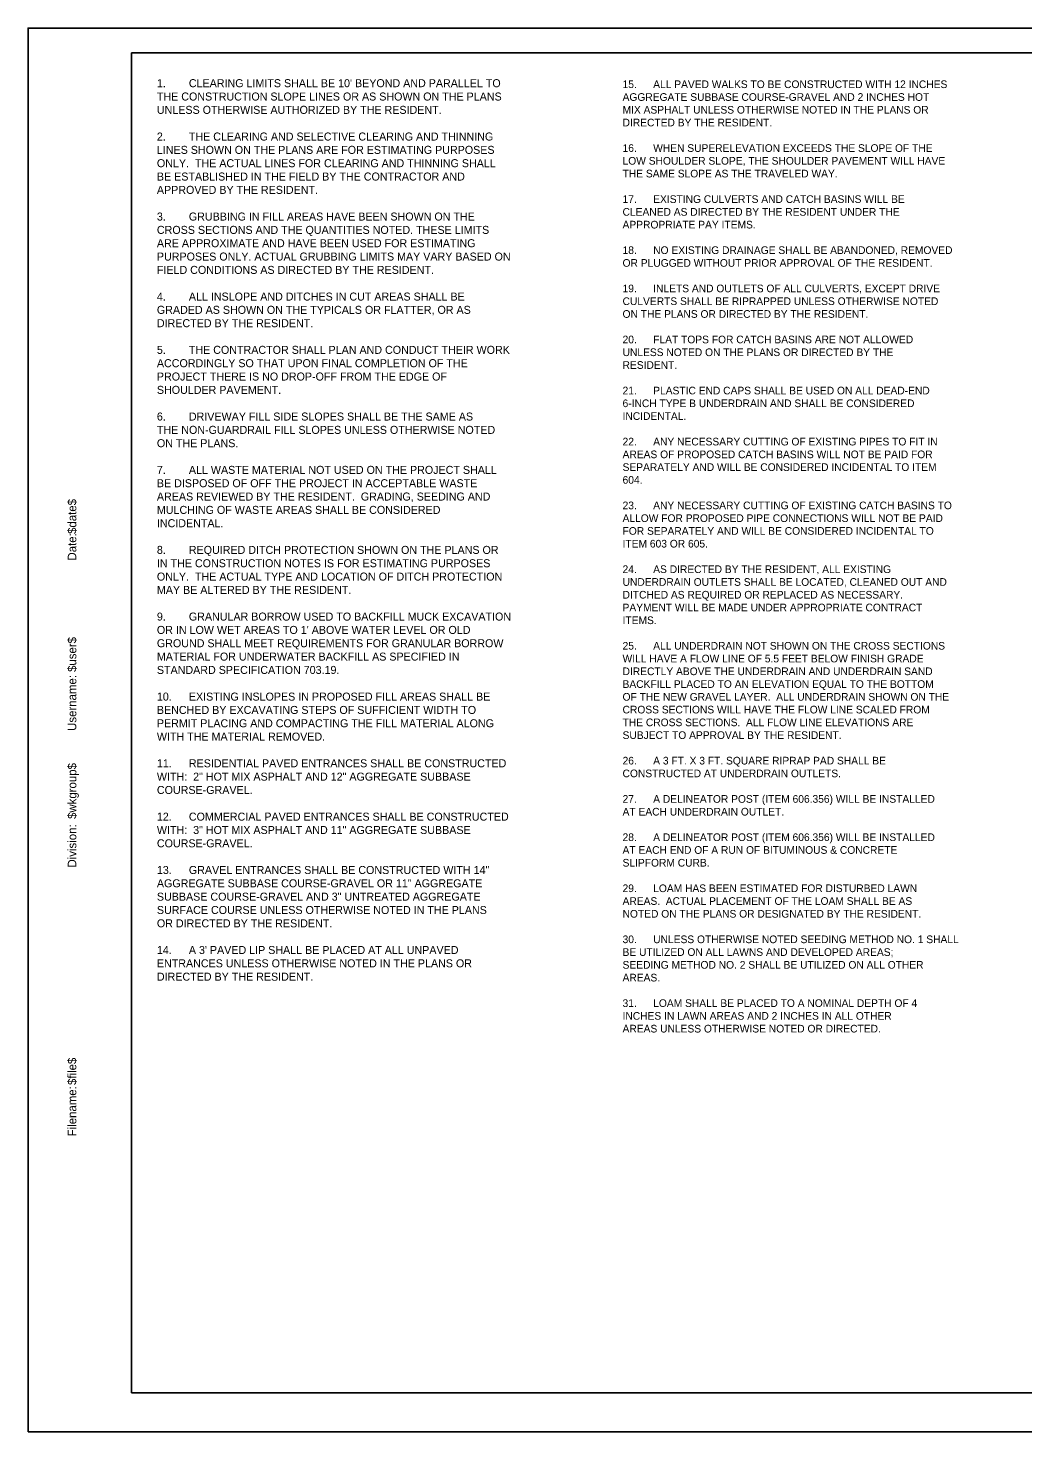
# Model space of a CAD drawing. Extents: x 2075518.1 to 2075585.6, y 1172412.5 to 1172434.5.
# Drawn here: x 2075518.14 to 2075533.73, y 1172412.49 to 1172434.49 of the extents above; entities that cross this region are included whole.
import ezdxf

# ---------------------------------------------------------------- set-up
doc = ezdxf.new("R2010")
doc.units = 0
for name, color, linetype in [('ANNOTATION', 7, 'Continuous'), ('Border', 7, 'Continuous'), ('PLOT BOUNDARY', 7, 'Continuous')]:
    doc.layers.add(name, color=color, linetype=linetype)

msp = doc.modelspace()

# ---------------------------------------------------------------- linework, layer by layer
at = {"layer": 'Border'}
for p, q in [((2075551.755, 1172434.098), (2075519.755, 1172434.098)), ((2075519.755, 1172434.098), (2075519.755, 1172413.098)), ((2075519.755, 1172413.098), (2075551.755, 1172413.098))]:
    msp.add_line(p, q, dxfattribs=at)
at = {"layer": 'PLOT BOUNDARY'}
msp.add_lwpolyline([(2075518.136, 1172412.486), (2075552.136, 1172412.486), (2075552.136, 1172434.486), (2075518.136, 1172434.486)], close=True, dxfattribs=at)

# ---------------------------------------------------------------- texts
at = {"layer": 'ANNOTATION'}
for s, height, p in [('1.', 0.1254, (2075520.155, 1172433.56)), ("CLEARING LIMITS SHALL BE 10' BEYOND AND PARALLEL TO ", 0.12539, (2075520.656, 1172433.56)), ('THE CONSTRUCTION SLOPE LINES OR AS SHOWN ON THE PLANS ', 0.12539, (2075520.155, 1172433.351)), ('AGGREGATE SUBBASE COURSE-GRAVEL AND 2 INCHES HOT ', 0.12, (2075527.453, 1172433.346)), ('15.', 0.12, (2075527.453, 1172433.546)), ('ALL PAVED WALKS TO BE CONSTRUCTED WITH 12 INCHES ', 0.12, (2075527.933, 1172433.546)), ('UNLESS OTHERWISE AUTHORIZED BY THE RESIDENT.  ', 0.12539, (2075520.155, 1172433.142)), ('MIX ASPHALT UNLESS OTHERWISE NOTED IN THE PLANS OR ', 0.12, (2075527.453, 1172433.146)), ('DIRECTED BY THE RESIDENT.', 0.12, (2075527.453, 1172432.946)), ('2.', 0.1254, (2075520.155, 1172432.724)), ('THE CLEARING AND SELECTIVE CLEARING AND THINNING ', 0.12539, (2075520.656, 1172432.724)), ('LINES SHOWN ON THE PLANS ARE FOR ESTIMATING PURPOSES ', 0.12539, (2075520.155, 1172432.515)), ('16.', 0.12, (2075527.453, 1172432.546)), ('WHEN SUPERELEVATION EXCEEDS THE SLOPE OF THE ', 0.12, (2075527.933, 1172432.546)), ('ONLY.  THE ACTUAL LINES FOR CLEARING AND THINNING SHALL ', 0.12539, (2075520.155, 1172432.306)), ('LOW SHOULDER SLOPE, THE SHOULDER PAVEMENT WILL HAVE ', 0.12, (2075527.453, 1172432.346)), ('BE ESTABLISHED IN THE FIELD BY THE CONTRACTOR AND ', 0.12539, (2075520.155, 1172432.097)), ('THE SAME SLOPE AS THE TRAVELED WAY.', 0.12, (2075527.453, 1172432.146)), ('APPROVED BY THE RESIDENT.', 0.12539, (2075520.155, 1172431.888)), ('17.', 0.12, (2075527.453, 1172431.746)), ('EXISTING CULVERTS AND CATCH BASINS WILL BE ', 0.12, (2075527.933, 1172431.746)), ('3.', 0.1254, (2075520.155, 1172431.47)), ('GRUBBING IN FILL AREAS HAVE BEEN SHOWN ON THE ', 0.12539, (2075520.656, 1172431.47)), ('CLEANED AS DIRECTED BY THE RESIDENT UNDER THE ', 0.12, (2075527.453, 1172431.546)), ('CROSS SECTIONS AND THE QUANTITIES NOTED. THESE LIMITS ', 0.12539, (2075520.155, 1172431.261)), ('APPROPRIATE PAY ITEMS.', 0.12, (2075527.453, 1172431.346)), ('ARE APPROXIMATE AND HAVE BEEN USED FOR ESTIMATING ', 0.12539, (2075520.155, 1172431.052)), ('18.', 0.12, (2075527.453, 1172430.946)), ('NO EXISTING DRAINAGE SHALL BE ABANDONED, REMOVED ', 0.12, (2075527.933, 1172430.946)), ('PURPOSES ONLY. ACTUAL GRUBBING LIMITS MAY VARY BASED ON ', 0.12539, (2075520.155, 1172430.843)), ('OR PLUGGED WITHOUT PRIOR APPROVAL OF THE RESIDENT.', 0.12, (2075527.453, 1172430.746)), ('FIELD CONDITIONS AS DIRECTED BY THE RESIDENT. ', 0.12539, (2075520.155, 1172430.634)), ('19.', 0.12, (2075527.453, 1172430.346)), ('INLETS AND OUTLETS OF ALL CULVERTS, EXCEPT DRIVE ', 0.12, (2075527.933, 1172430.346)), ('4.', 0.1254, (2075520.155, 1172430.216)), ('ALL INSLOPE AND DITCHES IN CUT AREAS SHALL BE ', 0.12539, (2075520.656, 1172430.216)), ('CULVERTS SHALL BE RIPRAPPED UNLESS OTHERWISE NOTED ', 0.12, (2075527.453, 1172430.146)), ('GRADED AS SHOWN ON THE TYPICALS OR FLATTER, OR AS ', 0.12539, (2075520.155, 1172430.008)), ('ON THE PLANS OR DIRECTED BY THE RESIDENT.', 0.12, (2075527.453, 1172429.946)), ('DIRECTED BY THE RESIDENT.', 0.12539, (2075520.155, 1172429.799)), ('5.', 0.1254, (2075520.155, 1172429.381)), ('THE CONTRACTOR SHALL PLAN AND CONDUCT THEIR WORK ', 0.12539, (2075520.656, 1172429.381)), ('20.', 0.12, (2075527.453, 1172429.546)), ('FLAT TOPS FOR CATCH BASINS ARE NOT ALLOWED ', 0.12, (2075527.933, 1172429.546)), ('ACCORDINGLY SO THAT UPON FINAL COMPLETION OF THE ', 0.12539, (2075520.155, 1172429.172)), ('UNLESS NOTED ON THE PLANS OR DIRECTED BY THE ', 0.12, (2075527.453, 1172429.346)), ('PROJECT THERE IS NO DROP-OFF FROM THE EDGE OF ', 0.12539, (2075520.155, 1172428.963)), ('RESIDENT.', 0.12, (2075527.453, 1172429.146)), ('SHOULDER PAVEMENT. ', 0.12539, (2075520.155, 1172428.754)), ('21.', 0.12, (2075527.453, 1172428.746)), ('PLASTIC END CAPS SHALL BE USED ON ALL DEAD-END ', 0.12, (2075527.933, 1172428.746)), ('6-INCH TYPE B UNDERDRAIN AND SHALL BE CONSIDERED ', 0.12, (2075527.453, 1172428.546)), ('6.', 0.1254, (2075520.155, 1172428.336)), ('DRIVEWAY FILL SIDE SLOPES SHALL BE THE SAME AS ', 0.12539, (2075520.656, 1172428.336)), ('INCIDENTAL.', 0.12, (2075527.453, 1172428.346)), ('THE NON-GUARDRAIL FILL SLOPES UNLESS OTHERWISE NOTED ', 0.12539, (2075520.155, 1172428.127)), ('ON THE PLANS.', 0.12539, (2075520.155, 1172427.918)), ('22.', 0.12, (2075527.453, 1172427.946)), ('ANY NECESSARY CUTTING OF EXISTING PIPES TO FIT IN ', 0.12, (2075527.933, 1172427.946)), ('AREAS OF PROPOSED CATCH BASINS WILL NOT BE PAID FOR ', 0.12, (2075527.453, 1172427.746)), ('7.', 0.1254, (2075520.155, 1172427.5)), ('ALL WASTE MATERIAL NOT USED ON THE PROJECT SHALL ', 0.12539, (2075520.656, 1172427.5)), ('SEPARATELY AND WILL BE CONSIDERED INCIDENTAL TO ITEM ', 0.12, (2075527.453, 1172427.546)), ('BE DISPOSED OF OFF THE PROJECT IN ACCEPTABLE WASTE ', 0.12539, (2075520.155, 1172427.291)), ('604.', 0.12, (2075527.453, 1172427.346)), ('AREAS REVIEWED BY THE RESIDENT.  GRADING, SEEDING AND ', 0.12539, (2075520.155, 1172427.082)), ('MULCHING OF WASTE AREAS SHALL BE CONSIDERED ', 0.12539, (2075520.155, 1172426.873)), ('ALLOW FOR PROPOSED PIPE CONNECTIONS WILL NOT BE PAID ', 0.12, (2075527.453, 1172426.746)), ('23.', 0.12, (2075527.453, 1172426.946)), ('ANY NECESSARY CUTTING OF EXISTING CATCH BASINS TO ', 0.12, (2075527.933, 1172426.946)), ('INCIDENTAL.', 0.12539, (2075520.155, 1172426.664)), ('FOR SEPARATELY AND WILL BE CONSIDERED INCIDENTAL TO ', 0.12, (2075527.453, 1172426.546)), ('ITEM 603 OR 605.', 0.12, (2075527.453, 1172426.346)), ('8.', 0.1254, (2075520.155, 1172426.246)), ('REQUIRED DITCH PROTECTION SHOWN ON THE PLANS OR ', 0.12539, (2075520.656, 1172426.246)), ('IN THE CONSTRUCTION NOTES IS FOR ESTIMATING PURPOSES ', 0.12539, (2075520.155, 1172426.037)), ('24.', 0.12, (2075527.453, 1172425.946)), ('AS DIRECTED BY THE RESIDENT, ALL EXISTING ', 0.12, (2075527.933, 1172425.946)), ('ONLY.  THE ACTUAL TYPE AND LOCATION OF DITCH PROTECTION ', 0.12539, (2075520.155, 1172425.828)), ('UNDERDRAIN OUTLETS SHALL BE LOCATED, CLEANED OUT AND ', 0.12, (2075527.453, 1172425.746)), ('MAY BE ALTERED BY THE RESIDENT.', 0.12539, (2075520.155, 1172425.619)), ('DITCHED AS REQUIRED OR REPLACED AS NECESSARY.   ', 0.12, (2075527.453, 1172425.546)), ('9.', 0.1254, (2075520.155, 1172425.201)), ('GRANULAR BORROW USED TO BACKFILL MUCK EXCAVATION ', 0.12539, (2075520.656, 1172425.201)), ('PAYMENT WILL BE MADE UNDER APPROPRIATE CONTRACT ', 0.12, (2075527.453, 1172425.346)), ("OR IN LOW WET AREAS TO 1' ABOVE WATER LEVEL OR OLD ", 0.12539, (2075520.155, 1172424.992)), ('ITEMS.', 0.12, (2075527.453, 1172425.146)), ('GROUND SHALL MEET REQUIREMENTS FOR GRANULAR BORROW ', 0.12539, (2075520.155, 1172424.783)), ('MATERIAL FOR UNDERWATER BACKFILL AS SPECIFIED IN ', 0.12539, (2075520.155, 1172424.574)), ('WILL HAVE A FLOW LINE OF 5.5 FEET BELOW FINISH GRADE ', 0.12, (2075527.453, 1172424.546)), ('25.', 0.12, (2075527.453, 1172424.746)), ('ALL UNDERDRAIN NOT SHOWN ON THE CROSS SECTIONS ', 0.12, (2075527.933, 1172424.746)), ('STANDARD SPECIFICATION 703.19.', 0.12539, (2075520.155, 1172424.365)), ('DIRECTLY ABOVE THE UNDERDRAIN AND UNDERDRAIN SAND ', 0.12, (2075527.453, 1172424.346)), ('BACKFILL PLACED TO AN ELEVATION EQUAL TO THE BOTTOM ', 0.12, (2075527.453, 1172424.146)), ('10.', 0.1254, (2075520.155, 1172423.947)), ('EXISTING INSLOPES IN PROPOSED FILL AREAS SHALL BE ', 0.12539, (2075520.656, 1172423.947)), ('OF THE NEW GRAVEL LAYER.  ALL UNDERDRAIN SHOWN ON THE ', 0.12, (2075527.453, 1172423.946)), ('BENCHED BY EXCAVATING STEPS OF SUFFICIENT WIDTH TO ', 0.12539, (2075520.155, 1172423.738)), ('CROSS SECTIONS WILL HAVE THE FLOW LINE SCALED FROM ', 0.12, (2075527.453, 1172423.746)), ('PERMIT PLACING AND COMPACTING THE FILL MATERIAL ALONG ', 0.12539, (2075520.155, 1172423.529)), ('THE CROSS SECTIONS.  ALL FLOW LINE ELEVATIONS ARE ', 0.12, (2075527.453, 1172423.546)), ('WITH THE MATERIAL REMOVED.', 0.12539, (2075520.155, 1172423.32)), ('SUBJECT TO APPROVAL BY THE RESIDENT.  ', 0.12, (2075527.453, 1172423.346)), ('11.', 0.1254, (2075520.155, 1172422.902)), ('RESIDENTIAL PAVED ENTRANCES SHALL BE CONSTRUCTED ', 0.12539, (2075520.656, 1172422.902)), ('26.', 0.12, (2075527.453, 1172422.946)), ('A 3 FT. X 3 FT. SQUARE RIPRAP PAD SHALL BE ', 0.12, (2075527.933, 1172422.946)), ('WITH:  2" HOT MIX ASPHALT AND 12" AGGREGATE SUBBASE ', 0.12539, (2075520.155, 1172422.693)), ('CONSTRUCTED AT UNDERDRAIN OUTLETS.', 0.12, (2075527.453, 1172422.746)), ('COURSE-GRAVEL.', 0.12539, (2075520.155, 1172422.484)), ('27.', 0.12, (2075527.453, 1172422.346)), ('A DELINEATOR POST (ITEM 606.356) WILL BE INSTALLED ', 0.12, (2075527.933, 1172422.346)), ('AT EACH UNDERDRAIN OUTLET.', 0.12, (2075527.453, 1172422.146)), ('12.', 0.1254, (2075520.155, 1172422.066)), ('COMMERCIAL PAVED ENTRANCES SHALL BE CONSTRUCTED ', 0.12539, (2075520.656, 1172422.066)), ('WITH:  3" HOT MIX ASPHALT AND 11" AGGREGATE SUBBASE ', 0.12539, (2075520.155, 1172421.857)), ('28.', 0.12, (2075527.453, 1172421.746)), ('A DELINEATOR POST (ITEM 606.356) WILL BE INSTALLED ', 0.12, (2075527.933, 1172421.746)), ('COURSE-GRAVEL.', 0.12539, (2075520.155, 1172421.648)), ('AT EACH END OF A RUN OF BITUMINOUS & CONCRETE ', 0.12, (2075527.453, 1172421.546)), ('SLIPFORM CURB.', 0.12, (2075527.453, 1172421.346)), ('AGGREGATE SUBBASE COURSE-GRAVEL OR 11" AGGREGATE ', 0.12539, (2075520.155, 1172421.021)), ('13.', 0.1254, (2075520.155, 1172421.23)), ('GRAVEL ENTRANCES SHALL BE CONSTRUCTED WITH 14" ', 0.12539, (2075520.656, 1172421.23)), ('SUBBASE COURSE-GRAVEL AND 3" UNTREATED AGGREGATE ', 0.12539, (2075520.155, 1172420.812)), ('29.', 0.12, (2075527.453, 1172420.946)), ('LOAM HAS BEEN ESTIMATED FOR DISTURBED LAWN ', 0.12, (2075527.933, 1172420.946)), ('SURFACE COURSE UNLESS OTHERWISE NOTED IN THE PLANS ', 0.12539, (2075520.155, 1172420.603)), ('AREAS.  ACTUAL PLACEMENT OF THE LOAM SHALL BE AS ', 0.12, (2075527.453, 1172420.746)), ('OR DIRECTED BY THE RESIDENT.', 0.12539, (2075520.155, 1172420.394)), ('NOTED ON THE PLANS OR DESIGNATED BY THE RESIDENT.', 0.12, (2075527.453, 1172420.546)), ('30.', 0.12, (2075527.453, 1172420.146)), ('UNLESS OTHERWISE NOTED SEEDING METHOD NO. 1 SHALL ', 0.12, (2075527.933, 1172420.146)), ('14.', 0.1254, (2075520.155, 1172419.976)), ("A 3' PAVED LIP SHALL BE PLACED AT ALL UNPAVED ", 0.12539, (2075520.656, 1172419.976)), ('BE UTILIZED ON ALL LAWNS AND DEVELOPED AREAS; ', 0.12, (2075527.453, 1172419.946)), ('ENTRANCES UNLESS OTHERWISE NOTED IN THE PLANS OR ', 0.12539, (2075520.155, 1172419.767)), ('SEEDING METHOD NO. 2 SHALL BE UTILIZED ON ALL OTHER ', 0.12, (2075527.453, 1172419.746)), ('DIRECTED BY THE RESIDENT.', 0.12539, (2075520.155, 1172419.558)), ('AREAS.', 0.12, (2075527.453, 1172419.546)), ('31.', 0.12, (2075527.453, 1172419.146)), ('LOAM SHALL BE PLACED TO A NOMINAL DEPTH OF 4 ', 0.12, (2075527.933, 1172419.146)), ('INCHES IN LAWN AREAS AND 2 INCHES IN ALL OTHER ', 0.12, (2075527.453, 1172418.946)), ('AREAS UNLESS OTHERWISE NOTED OR DIRECTED.', 0.12, (2075527.453, 1172418.746))]:
    msp.add_text(s, height=height, dxfattribs=at).set_placement(p)
at = {"layer": 'Border'}
for s, p in [('$date$', (2075518.892, 1172426.559)), ('Date:', (2075518.892, 1172426.142)), ('$user$', (2075518.892, 1172424.396)), ('Username:', (2075518.892, 1172423.472)), ('$wkgroup$', (2075518.892, 1172422.092)), ('Division:', (2075518.892, 1172421.331)), ('$file$', (2075518.892, 1172417.923)), ('Filename:', (2075518.892, 1172417.118))]:
    msp.add_text(s, height=0.1339, rotation=90, dxfattribs=at).set_placement(p)

doc.saveas('drawing.dxf')
